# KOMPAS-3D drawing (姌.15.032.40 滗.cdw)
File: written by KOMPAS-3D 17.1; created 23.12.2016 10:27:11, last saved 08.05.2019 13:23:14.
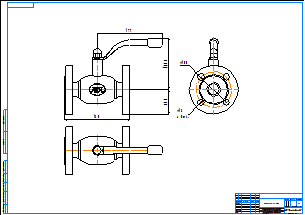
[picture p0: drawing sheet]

Sheet 1: A1, landscape

Title block, sheet 1: name: КШ.15.032.40 фф; material: Внимание! Данный продукт является объектом авторского права ООО «Торговый Дом АДЛ». / Запрещается изменение, копирование, распространение / (в том числе путем копирования на другие сайты и ресурсы в Интернете) / или любое иное использование информации и объектов без предварительного / согласия правообладателя (ООО «Торговый Дом АДЛ»).; sheets: 1; organisation: ООО "Торговый дом АДЛ"; sheet format: A1; stored path: C:\Users\tra\Desktop\2д чертежи\Шаровые краны БИВАЛ\КШ_Бивал_серия_14_15\KOMPAS_2D\КШ.15.032.40 фф.cdw

Views: Вид 1, Проекционный вид 2, Проекционный вид 3
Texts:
  Klimkovich
  ADL
Dimensions and other numbers on the sheet: 180; 179; 142,6; 67,5; 100; 18; 4 Отв.; 1:1; 1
